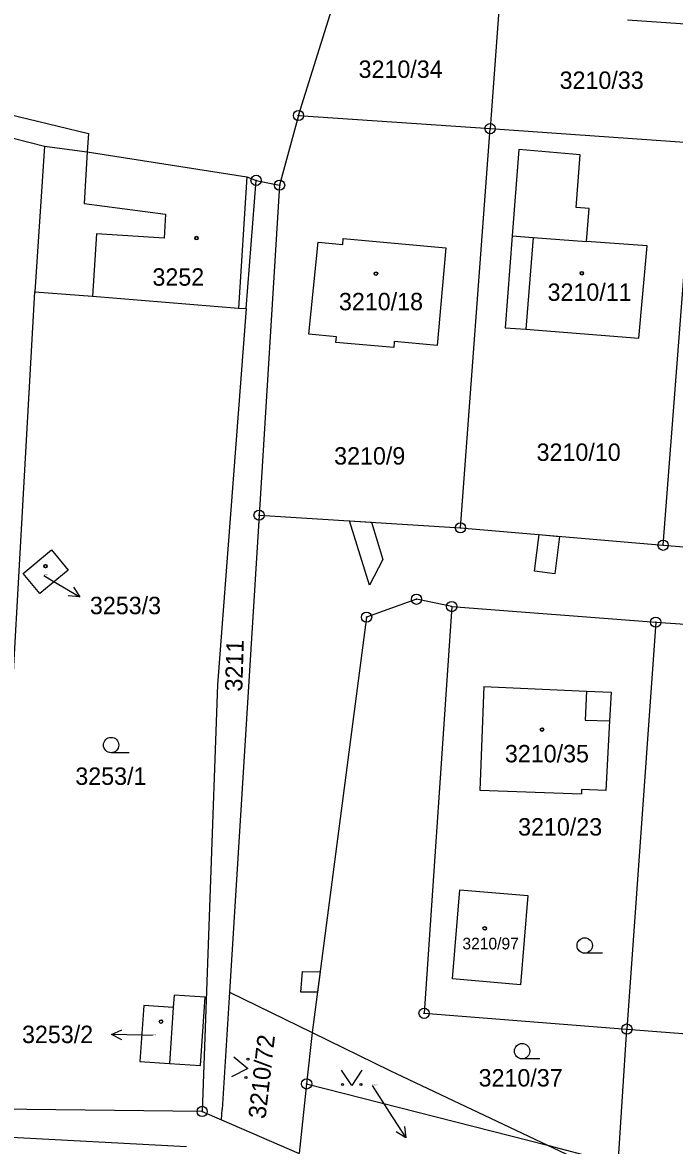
# Model space of a CAD drawing. Extents: x -593183 to -588034, y -1130415 to -1124994.
# Drawn here: x -592330.3 to -592266.6, y -1128134.3 to -1128024.6 of the extents above; entities that cross this region are included whole.
import ezdxf

# ---------------------------------------------------------------- set-up
doc = ezdxf.new("R2010")
doc.units = 0
for name, color, linetype in [('Vrstva 1', 7, 'Continuous'), ('Vrstva 16', 7, 'Continuous'), ('Vrstva 18', 7, 'Continuous'), ('Vrstva 19', 7, 'Continuous'), ('Vrstva 24', 7, 'Continuous'), ('Vrstva 25', 7, 'Continuous'), ('Vrstva 27', 7, 'Continuous'), ('Vrstva 4', 7, 'Continuous')]:
    doc.layers.add(name, color=color, linetype=linetype)

msp = doc.modelspace()

# ---------------------------------------------------------------- linework, layer by layer
at = {"layer": 'Vrstva 1'}
for p, q in [((-592303.31, -1128033.68), (-592299.73, -1128022.21)), ((-592283.73, -1128023.39), (-592284.59, -1128034.96)), ((-592271.16, -1128024.32), (-592263.76, -1128024.86)), ((-592342.84, -1128030.86), (-592323.85, -1128035.42)), ((-592337.69, -1128034.26), (-592328.15, -1128036.68)), ((-592303.31, -1128033.68), (-592305.16, -1128040.48)), ((-592303.31, -1128033.68), (-592284.59, -1128034.96)), ((-592323.85, -1128035.42), (-592323.96, -1128037.24)), ((-592287.49, -1128073.95), (-592284.59, -1128034.96)), ((-592284.59, -1128034.96), (-592264.64, -1128036.33)), ((-592328.15, -1128036.68), (-592329.08, -1128050.91)), ((-592328.15, -1128036.68), (-592323.96, -1128037.24)), ((-592267.68, -1128075.65), (-592264.64, -1128036.33)), ((-592323.96, -1128037.24), (-592308.38, -1128039.68)), ((-592281.77, -1128036.99), (-592282.43, -1128045.42)), ((-592275.79, -1128037.51), (-592281.77, -1128036.99)), ((-592276.19, -1128042.65), (-592275.79, -1128037.51)), ((-592308.42, -1128052.54), (-592307.46, -1128040.01)), ((-592308.38, -1128039.68), (-592307.46, -1128040.01)), ((-592307.46, -1128040.01), (-592305.16, -1128040.48)), ((-592305.16, -1128040.48), (-592307.17, -1128072.71)), ((-592274.9, -1128042.75), (-592276.19, -1128042.65)), ((-592275.15, -1128045.99), (-592274.9, -1128042.75)), ((-592282.43, -1128045.42), (-592283.1, -1128054.43)), ((-592302.31, -1128055.02), (-592301.4, -1128046.06)), ((-592301.4, -1128046.06), (-592298.99, -1128046.27)), ((-592298.99, -1128046.27), (-592298.94, -1128045.7)), ((-592298.94, -1128045.7), (-592288.92, -1128046.59)), ((-592288.92, -1128046.59), (-592289.76, -1128056.13)), ((-592269.22, -1128046.41), (-592275.15, -1128045.99)), ((-592270.04, -1128055.43), (-592269.22, -1128046.41)), ((-592333.63, -1128130.7), (-592329.08, -1128050.91)), ((-592329.08, -1128050.91), (-592323.45, -1128051.31)), ((-592323.45, -1128051.31), (-592309.17, -1128052.48)), ((-592308.42, -1128052.54), (-592311.22, -1128089.27)), ((-592309.17, -1128052.48), (-592308.42, -1128052.54)), ((-592299.61, -1128055.3), (-592302.31, -1128055.02)), ((-592299.66, -1128055.84), (-592299.61, -1128055.3)), ((-592283.1, -1128054.43), (-592281.09, -1128054.55)), ((-592281.09, -1128054.55), (-592270.04, -1128055.43)), ((-592294.01, -1128056.34), (-592299.66, -1128055.84)), ((-592293.96, -1128055.76), (-592294.01, -1128056.34)), ((-592289.76, -1128056.13), (-592293.96, -1128055.76)), ((-592307.17, -1128072.71), (-592310.07, -1128119.3)), ((-592307.17, -1128072.71), (-592287.49, -1128073.95)), ((-592287.49, -1128073.95), (-592267.68, -1128075.65)), ((-592330.23, -1128078.4), (-592327.45, -1128076.11)), ((-592327.45, -1128076.11), (-592325.83, -1128078.08)), ((-592267.68, -1128075.65), (-592247.79, -1128077.14)), ((-592328.61, -1128080.37), (-592330.23, -1128078.4)), ((-592325.83, -1128078.08), (-592328.61, -1128080.37)), ((-592291.78, -1128080.92), (-592296.66, -1128082.67)), ((-592288.34, -1128081.64), (-592291.78, -1128080.92)), ((-592288.34, -1128081.64), (-592291.04, -1128121.36)), ((-592288.34, -1128081.64), (-592268.4, -1128083.16)), ((-592296.66, -1128082.67), (-592301.99, -1128123.24)), ((-592268.4, -1128083.16), (-592271.21, -1128122.9)), ((-592268.4, -1128083.16), (-592248.45, -1128084.59)), ((-592311.22, -1128089.27), (-592312.73, -1128130.94)), ((-592285.19, -1128089.44), (-592285.58, -1128099.56)), ((-592285.19, -1128089.44), (-592275.15, -1128089.9)), ((-592275.15, -1128089.9), (-592272.75, -1128090.01)), ((-592272.75, -1128090.01), (-592272.91, -1128092.8)), ((-592272.91, -1128092.8), (-592273.29, -1128099.59)), ((-592285.58, -1128099.56), (-592275.66, -1128099.94)), ((-592275.64, -1128099.49), (-592275.66, -1128099.94)), ((-592273.29, -1128099.59), (-592275.64, -1128099.49)), ((-592315.46, -1128119.58), (-592315.55, -1128120.8)), ((-592312.43, -1128119.79), (-592315.46, -1128119.58)), ((-592312.89, -1128126.47), (-592312.43, -1128119.79)), ((-592310.07, -1128119.3), (-592310.79, -1128130.74)), ((-592310.07, -1128119.3), (-592301.99, -1128123.24)), ((-592318.43, -1128120.6), (-592318.81, -1128126.06)), ((-592315.55, -1128120.8), (-592318.43, -1128120.6)), ((-592291.04, -1128121.36), (-592271.21, -1128122.9)), ((-592301.99, -1128123.24), (-592302.52, -1128128.26)), ((-592301.99, -1128123.24), (-592294.4, -1128126.95)), ((-592272.08, -1128136.07), (-592271.21, -1128122.9)), ((-592271.21, -1128122.9), (-592251.38, -1128124.44)), ((-592318.81, -1128126.06), (-592315.93, -1128126.26)), ((-592315.93, -1128126.26), (-592312.89, -1128126.47)), ((-592294.4, -1128126.95), (-592278.98, -1128134.23)), ((-592302.52, -1128128.26), (-592303.25, -1128135.06)), ((-592302.52, -1128128.26), (-592278.98, -1128134.23)), ((-592312.73, -1128130.94), (-592333.63, -1128130.7)), ((-592312.73, -1128130.94), (-592310.85, -1128131.76)), ((-592310.85, -1128131.76), (-592310.79, -1128130.74)), ((-592310.85, -1128131.76), (-592303.25, -1128135.06)), ((-592278.98, -1128134.23), (-592272.08, -1128136.07)), ((-592278.98, -1128134.23), (-592272.17, -1128137.44))]:
    msp.add_line(p, q, dxfattribs=at)
msp.add_lwpolyline([(-592287.53, -1128109.29), (-592280.9, -1128109.85), (-592281.63, -1128118.59), (-592288.25, -1128118.01), (-592287.53, -1128109.29)], dxfattribs=at)
at = {"layer": 'Vrstva 16'}
for p, q in [((-592328.2, -1128078.6), (-592327.28, -1128079.15)), ((-592317.58, -1128123.52), (-592318.58, -1128123.5)), ((-592296.11, -1128128.41), (-592294.44, -1128131))]:
    msp.add_line(p, q, dxfattribs=at)
at = {"layer": 'Vrstva 24'}
for centre, radius in [((-592303.31, -1128033.68), 0.5), ((-592303.31, -1128033.68), 0.0327), ((-592284.59, -1128034.96), 0.5), ((-592284.59, -1128034.96), 0.0327), ((-592307.46, -1128040.01), 0.5), ((-592307.46, -1128040.01), 0.0327), ((-592305.16, -1128040.48), 0.5), ((-592305.16, -1128040.48), 0.0327), ((-592307.17, -1128072.71), 0.5), ((-592307.17, -1128072.71), 0.0327), ((-592287.49, -1128073.95), 0.5), ((-592287.49, -1128073.95), 0.0327), ((-592267.68, -1128075.65), 0.5), ((-592267.68, -1128075.65), 0.0327), ((-592291.78, -1128080.92), 0.5), ((-592291.78, -1128080.92), 0.0327), ((-592288.34, -1128081.64), 0.5), ((-592288.34, -1128081.64), 0.0327), ((-592296.66, -1128082.67), 0.5), ((-592296.66, -1128082.67), 0.0327), ((-592268.4, -1128083.16), 0.5), ((-592268.4, -1128083.16), 0.0327), ((-592291.04, -1128121.36), 0.5), ((-592291.04, -1128121.36), 0.0327), ((-592271.21, -1128122.9), 0.5), ((-592271.21, -1128122.9), 0.0327), ((-592302.52, -1128128.26), 0.5), ((-592302.52, -1128128.26), 0.0327), ((-592312.73, -1128130.94), 0.5), ((-592312.73, -1128130.94), 0.0327)]:
    msp.add_circle(centre, radius, dxfattribs=at)
at = {"layer": 'Vrstva 25'}
for p, q in [((-592327.28, -1128079.15), (-592324.7, -1128080.68)), ((-592319.88, -1128095.91), (-592321.63, -1128095.91)), ((-592273.59, -1128115.49), (-592275.34, -1128115.49)), ((-592318.58, -1128123.5), (-592321.58, -1128123.44)), ((-592279.71, -1128125.81), (-592281.46, -1128125.81)), ((-592294.44, -1128131), (-592292.82, -1128133.52))]:
    msp.add_line(p, q, dxfattribs=at)
for points in [[(-592325.31, -1128079.74), (-592324.7, -1128080.68), (-592325.82, -1128080.6)], [(-592320.59, -1128123.96), (-592321.58, -1128123.44), (-592320.57, -1128122.96)], [(-592309.63, -1128125.6), (-592308.25, -1128126.76), (-592309.85, -1128127.58)], [(-592297.11, -1128126.91), (-592298.11, -1128128.41), (-592299.11, -1128126.91)], [(-592292.94, -1128132.41), (-592292.82, -1128133.52), (-592293.78, -1128132.95)]]:
    msp.add_lwpolyline(points, dxfattribs=at)
for centre, radius in [((-592313.28, -1128045.65), 0.175), ((-592313.28, -1128045.65), 0.15), ((-592295.75, -1128049.12), 0.175), ((-592295.75, -1128049.12), 0.15), ((-592275.62, -1128049.08), 0.175), ((-592275.62, -1128049.08), 0.15), ((-592328.04, -1128077.69), 0.175), ((-592328.04, -1128077.69), 0.15), ((-592279.51, -1128093.65), 0.175), ((-592279.51, -1128093.65), 0.15), ((-592321.63, -1128095.16), 0.75), ((-592285.11, -1128113.06), 0.175), ((-592285.11, -1128113.06), 0.15), ((-592275.34, -1128114.74), 0.75), ((-592316.75, -1128122.17), 0.175), ((-592316.75, -1128122.17), 0.15), ((-592281.46, -1128125.06), 0.75), ((-592308.25, -1128125.85), 0.1), ((-592308.45, -1128127.64), 0.1), ((-592299.01, -1128128.31), 0.1), ((-592297.21, -1128128.31), 0.1)]:
    msp.add_circle(centre, radius, dxfattribs=at)
at = {"layer": 'Vrstva 27'}
for p, q in [((-592296.37, -1128079.56), (-592298.32, -1128073.27)), ((-592298.32, -1128073.27), (-592296.19, -1128073.4)), ((-592296.19, -1128073.4), (-592295.06, -1128077.03)), ((-592280.25, -1128078.19), (-592279.8, -1128074.61)), ((-592279.8, -1128074.61), (-592277.8, -1128074.78)), ((-592277.8, -1128074.78), (-592278.27, -1128078.44)), ((-592295.06, -1128077.03), (-592296.37, -1128079.56)), ((-592278.27, -1128078.44), (-592280.25, -1128078.19)), ((-592303.08, -1128119.28), (-592302.92, -1128117.29)), ((-592302.92, -1128117.29), (-592301.21, -1128117.32)), ((-592301.21, -1128117.32), (-592301.47, -1128119.31)), ((-592301.47, -1128119.31), (-592303.08, -1128119.28))]:
    msp.add_line(p, q, dxfattribs=at)
at = {"layer": 'Vrstva 4'}
for p, q in [((-592323.96, -1128037.24), (-592324.25, -1128042.26)), ((-592308.38, -1128039.68), (-592309.17, -1128052.48)), ((-592324.25, -1128042.26), (-592316.31, -1128043.31)), ((-592316.31, -1128043.31), (-592316.46, -1128045.66)), ((-592323.06, -1128045.24), (-592323.45, -1128051.31)), ((-592316.46, -1128045.66), (-592323.06, -1128045.24)), ((-592282.43, -1128045.42), (-592280.39, -1128045.58)), ((-592280.39, -1128045.58), (-592281.09, -1128054.55)), ((-592280.39, -1128045.58), (-592275.15, -1128045.99)), ((-592275.15, -1128089.9), (-592275.28, -1128092.72)), ((-592275.28, -1128092.72), (-592272.91, -1128092.8)), ((-592315.55, -1128120.8), (-592315.93, -1128126.26)), ((-592314.26, -1128134.41), (-592332.63, -1128133.42))]:
    msp.add_line(p, q, dxfattribs=at)

# ---------------------------------------------------------------- texts
at = {"layer": 'Vrstva 16'}
for s, p in [('3253/3', (-592323.7, -1128082.38)), ('3253/2', (-592330.34, -1128124.27))]:
    msp.add_text(s, height=1.7, dxfattribs=at).set_placement(p)
at = {"layer": 'Vrstva 18'}
for s, height, p in [('3210/34', 1.7, (-592297.44, -1128030)), ('3210/33', 1.7, (-592277.79, -1128031.08)), ('3210/9', 1.7, (-592299.83, -1128067.77)), ('3210/10', 1.7, (-592280.04, -1128067.41)), ('3253/1', 1.7, (-592325.13, -1128099.05)), ('3210/23', 1.7, (-592281.85, -1128104)), ('3210/37', 1.7, (-592285.71, -1128128.51)), ('3210/38', 0.1, (-592296.11, -1128128.41))]:
    msp.add_text(s, height=height, dxfattribs=at).set_placement(p)
for s, rotation, p in [('3211', 88.2521, (-592308.81, -1128089.95)), ('3210/72', 83.4802, (-592306.54, -1128131.72))]:
    msp.add_text(s, height=1.7, rotation=rotation, dxfattribs=at).set_placement(p)
at = {"layer": 'Vrstva 19'}
for s, height, p in [('3252', 1.7, (-592317.59, -1128050.3)), ('3210/18', 1.7, (-592299.36, -1128052.7)), ('3210/11', 1.7, (-592278.97, -1128051.78)), ('3253/3', 0.1, (-592328.2, -1128078.6)), ('3210/35', 1.7, (-592283.14, -1128096.85)), ('3210/97', 1.14, (-592287.29, -1128115.12)), ('3253/2', 0.1, (-592317.58, -1128123.52))]:
    msp.add_text(s, height=height, dxfattribs=at).set_placement(p)

doc.saveas('drawing.dxf')
